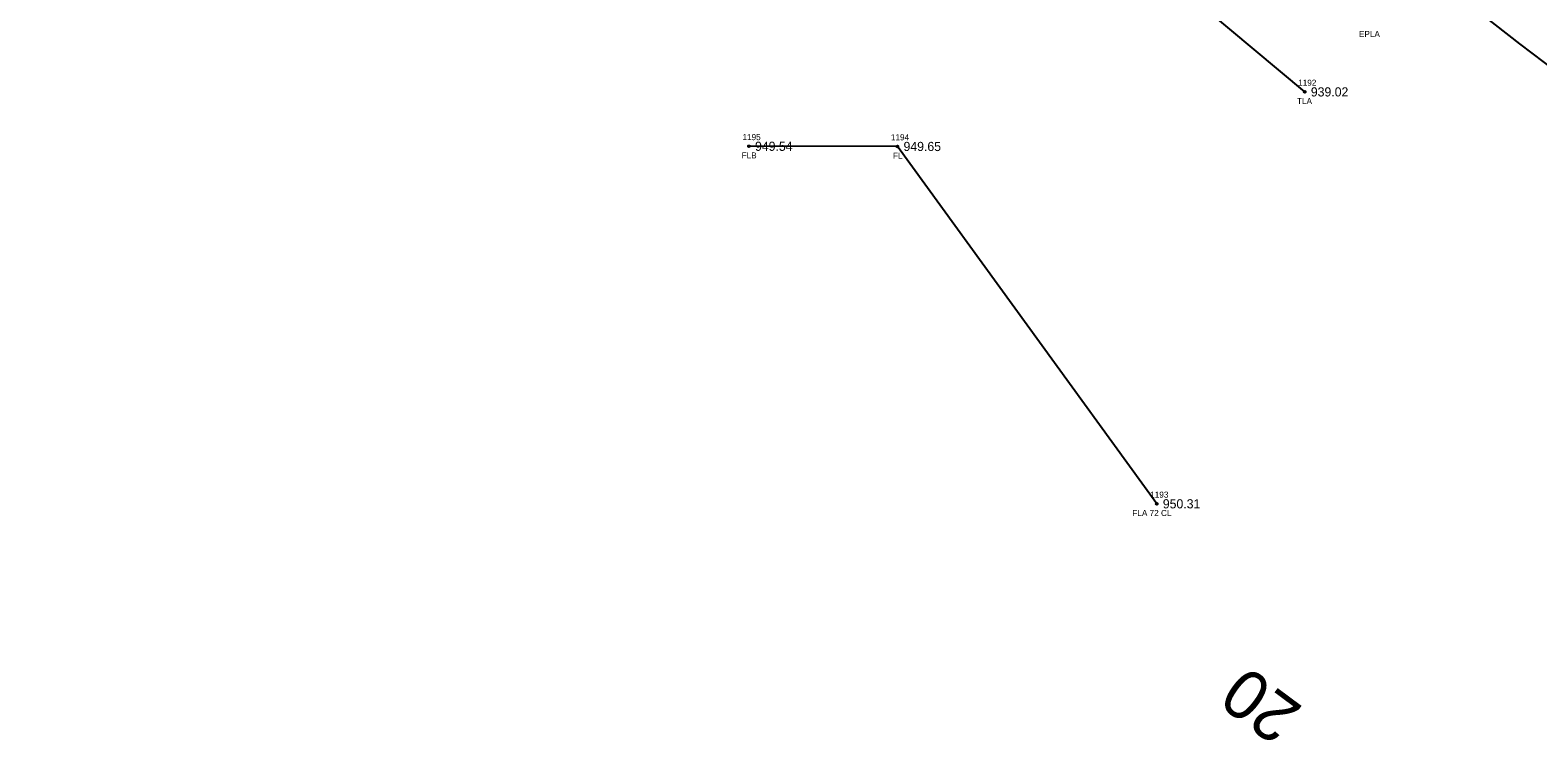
# Model space of a CAD drawing. Extents: x 1393163 to 1398407, y 1072670 to 1074651.
# Drawn here: x 1396893.9 to 1397140.6, y 1073938.1 to 1074054.9 of the extents above; entities that cross this region are included whole.
import ezdxf

# ---------------------------------------------------------------- set-up
doc = ezdxf.new("R2010")
doc.units = 0
for name, color, linetype in [('RD_EX_Fence_Other', 7, 'Continuous'), ('RD_EX_Fence_Other_txCode', 7, 'Continuous'), ('RD_EX_Road_txCode', 7, 'Continuous'), ('RD_EX_TX_Fence_Other_ELEV', 7, 'Continuous'), ('RD_EX_TX_VEG_ELEV', 7, 'Continuous'), ('RD_EX_VEG', 7, 'Continuous'), ('RD_EX_VEG_txCode', 7, 'Continuous'), ('RD_HC_Cl', 7, 'Continuous'), ('RD_HC_TX_Sta50', 7, 'Continuous'), ('RD_SMD_Locator', 7, 'Continuous')]:
    doc.layers.add(name, color=color, linetype=linetype)

msp = doc.modelspace()

# ---------------------------------------------------------------- linework, layer by layer
at = {"layer": 'RD_EX_Fence_Other'}
msp.add_lwpolyline([(1397078.23, 1073977.4), (1397035.8, 1074035.87), (1397011.51, 1074035.9)], dxfattribs=at)
at = {"layer": 'RD_EX_VEG'}
msp.add_lwpolyline([(1397102.45, 1074044.8), (1397023.2, 1074111.05), (1396958.86, 1074125.87), (1396923.23, 1074126.87), (1396893.89, 1074108.8)], dxfattribs=at)
at = {"layer": 'RD_HC_Cl'}
msp.add_arc((1398300.81, 1075567), 1909.5, 228.82706, 238.54375, dxfattribs=at)
at = {"layer": 'RD_SMD_Locator'}
for centre in [(1397102.45, 1074044.8), (1397011.51, 1074035.9), (1397035.8, 1074035.87), (1397078.23, 1073977.4)]:
    msp.add_circle(centre, 0.15, dxfattribs=at)

# ---------------------------------------------------------------- texts
at = {"layer": 'RD_EX_Fence_Other_txCode'}
for s, p in [('1195', (1397010.45, 1074036.9)), ('1194', (1397034.74, 1074036.87)), ('FLB', (1397010.31, 1074033.9)), ('FL', (1397035.07, 1074033.87)), ('1193', (1397077.17, 1073978.4)), ('FLA 72 CL', (1397074.25, 1073975.4))]:
    msp.add_text(s, height=1, dxfattribs=at).set_placement(p)
at = {"layer": 'RD_EX_Road_txCode'}
msp.add_text('EPLA', height=1, dxfattribs=at).set_placement((1397111.33, 1074053.78))
at = {"layer": 'RD_EX_TX_Fence_Other_ELEV'}
for s, p in [('949.54', (1397012.51, 1074035.15)), ('949.65', (1397036.8, 1074035.12)), ('950.31', (1397079.23, 1073976.65))]:
    msp.add_text(s, height=1.5, dxfattribs=at).set_placement(p)
at = {"layer": 'RD_EX_TX_VEG_ELEV'}
msp.add_text('939.02', height=1.5, dxfattribs=at).set_placement((1397103.45, 1074044.05))
at = {"layer": 'RD_EX_VEG_txCode'}
for s, p in [('1192', (1397101.38, 1074045.8)), ('TLA', (1397101.19, 1074042.8))]:
    msp.add_text(s, height=1, dxfattribs=at).set_placement(p)
at = {"layer": 'RD_HC_TX_Sta50'}
msp.add_text('20', height=8, rotation=143.3927, dxfattribs=at).set_placement((1397102.37, 1073944.02))

doc.saveas('drawing.dxf')
